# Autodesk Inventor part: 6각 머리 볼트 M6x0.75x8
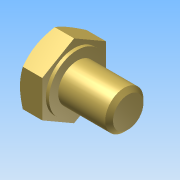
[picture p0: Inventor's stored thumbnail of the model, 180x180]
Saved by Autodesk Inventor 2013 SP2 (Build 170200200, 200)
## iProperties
Created: 2025-10
Part Number: 6각 머리 볼트 M6x0.75x8
Material: Generic
Document SubType Name: Modeling
Designer: 601
Density: 1 g/cm^3
Author: 601
변환 표준: STEP AP214IS
전처리기: Build: 200, Release: 2013 SP2 Update 6 - Date: Thu 07/17/2014
전송 단위: 밀리미터
불확실성: 0.01
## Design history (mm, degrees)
node "6각 머리 볼트 M6x0.75x81"
body "Solid1"
node "기준1"
